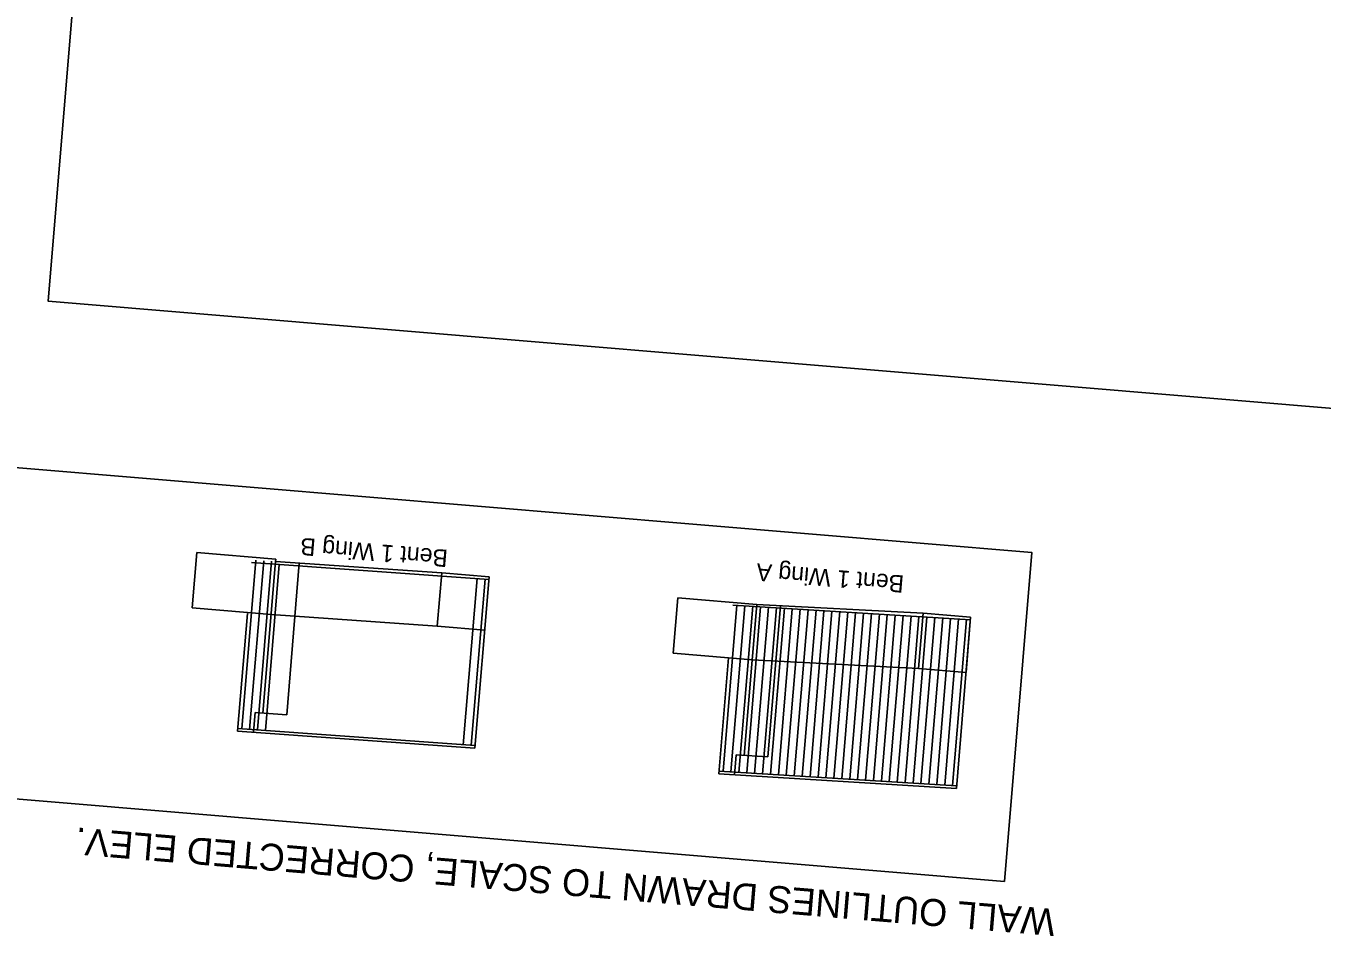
# Model space of a CAD drawing. Extents: x 1313815 to 1314857, y 2089008 to 2089414.
# Drawn here: x 1313873.4 to 1313955.2, y 2089107.2 to 2089164.5 of the extents above; entities that cross this region are included whole.
import ezdxf

# ---------------------------------------------------------------- set-up
doc = ezdxf.new("R2010")
doc.units = 0
for name, color, linetype in [('B-Gen-Construction Line', 7, 'Continuous'), ('B-Gen-Hidden', 7, 'Continuous'), ('B-Gen-Rebar', 7, 'Continuous'), ('B-Gen-Viewport', 7, 'Continuous'), ('B-Sub-Abutment Cap (Hidden)', 7, 'Continuous'), ('B-Sub-Wingwall', 7, 'Continuous')]:
    doc.layers.add(name, color=color, linetype=linetype)

msp = doc.modelspace()

# ---------------------------------------------------------------- linework, layer by layer
at = {"layer": 'B-Gen-Construction Line'}
for p, q in [((1313887.672, 2089130.726), (1313902.635, 2089129.658)), ((1313918.009, 2089128.043), (1313932.984, 2089127.125)), ((1313886.799, 2089120.263), (1313901.762, 2089119.194)), ((1313917.135, 2089117.58), (1313932.111, 2089116.661))]:
    msp.add_line(p, q, dxfattribs=at)
at = {"layer": 'B-Gen-Hidden'}
for p, q in [((1313890.678, 2089130.679), (1313889.882, 2089121.137)), ((1313921.016, 2089128.002), (1313920.22, 2089118.474)), ((1313887.782, 2089120.025), (1313887.887, 2089121.28)), ((1313887.783, 2089120.035), (1313887.886, 2089121.266)), ((1313887.887, 2089121.28), (1313889.882, 2089121.137)), ((1313886.785, 2089120.097), (1313901.748, 2089119.028)), ((1313918.12, 2089117.352), (1313918.224, 2089118.598)), ((1313918.12, 2089117.352), (1313918.222, 2089118.583)), ((1313918.224, 2089118.598), (1313920.22, 2089118.474)), ((1313917.121, 2089117.414), (1313932.097, 2089116.495))]:
    msp.add_line(p, q, dxfattribs=at)
at = {"layer": 'B-Gen-Rebar'}
for p, q in [((1313887.048, 2089120.245), (1313887.935, 2089130.875)), ((1313887.547, 2089120.209), (1313888.434, 2089130.839)), ((1313888.045, 2089120.174), (1313888.933, 2089130.803)), ((1313888.544, 2089120.138), (1313889.418, 2089130.602)), ((1313901.013, 2089119.248), (1313901.887, 2089129.711)), ((1313901.512, 2089119.212), (1313902.386, 2089129.676)), ((1313917.387, 2089117.586), (1313918.258, 2089128.029)), ((1313917.885, 2089117.545), (1313918.757, 2089127.998)), ((1313918.383, 2089117.503), (1313919.257, 2089127.967)), ((1313918.882, 2089117.473), (1313919.756, 2089127.936)), ((1313919.381, 2089117.442), (1313920.255, 2089127.906)), ((1313919.881, 2089117.411), (1313920.754, 2089127.875)), ((1313920.38, 2089117.381), (1313921.253, 2089127.844)), ((1313920.879, 2089117.35), (1313921.752, 2089127.814)), ((1313921.378, 2089117.32), (1313922.252, 2089127.783)), ((1313921.877, 2089117.289), (1313922.751, 2089127.753)), ((1313922.377, 2089117.258), (1313923.25, 2089127.722)), ((1313922.876, 2089117.228), (1313923.749, 2089127.691)), ((1313923.375, 2089117.197), (1313924.248, 2089127.661)), ((1313923.874, 2089117.166), (1313924.748, 2089127.63)), ((1313924.373, 2089117.136), (1313925.247, 2089127.599)), ((1313924.872, 2089117.105), (1313925.746, 2089127.569)), ((1313925.372, 2089117.074), (1313926.245, 2089127.538)), ((1313925.871, 2089117.044), (1313926.744, 2089127.507)), ((1313926.37, 2089117.013), (1313927.243, 2089127.477)), ((1313926.869, 2089116.983), (1313927.743, 2089127.446)), ((1313927.368, 2089116.952), (1313928.242, 2089127.416)), ((1313927.868, 2089116.921), (1313928.741, 2089127.385)), ((1313928.367, 2089116.891), (1313929.24, 2089127.354)), ((1313928.866, 2089116.86), (1313929.739, 2089127.324)), ((1313929.365, 2089116.829), (1313930.239, 2089127.293)), ((1313929.864, 2089116.799), (1313930.738, 2089127.262)), ((1313930.363, 2089116.768), (1313931.237, 2089127.232)), ((1313930.863, 2089116.738), (1313931.736, 2089127.201)), ((1313931.362, 2089116.707), (1313932.235, 2089127.171)), ((1313931.861, 2089116.676), (1313932.734, 2089127.14))]:
    msp.add_line(p, q, dxfattribs=at)
at = {"layer": 'B-Gen-Viewport'}
for points in [[(1314020.803, 2089135.014), (1313874.841, 2089147.198), (1313881.076, 2089221.883), (1314027.037, 2089209.699)], [(1313935.133, 2089110.63), (1313815.428, 2089120.622), (1313817.158, 2089141.347), (1313936.863, 2089131.354)]]:
    msp.add_lwpolyline(points, close=True, dxfattribs=at)
at = {"layer": 'B-Sub-Abutment Cap (Hidden)'}
for p, q in [((1313888.386, 2089121.242), (1313889.182, 2089130.786)), ((1313899.378, 2089126.708), (1313899.659, 2089130.074)), ((1313887.409, 2089127.581), (1313888.904, 2089127.456)), ((1313888.904, 2089127.456), (1313899.378, 2089126.708)), ((1313918.722, 2089118.559), (1313919.518, 2089128.091)), ((1313929.717, 2089124.052), (1313930.008, 2089127.54)), ((1313899.378, 2089126.708), (1313902.368, 2089126.458)), ((1313932.998, 2089127.291), (1313932.707, 2089123.803)), ((1313917.732, 2089124.728), (1313919.227, 2089124.604)), ((1313919.227, 2089124.604), (1313929.717, 2089124.052)), ((1313932.707, 2089123.803), (1313929.717, 2089124.052))]:
    msp.add_line(p, q, dxfattribs=at)
at = {"layer": 'B-Sub-Wingwall'}
for p, q in [((1313884.213, 2089131.36), (1313883.922, 2089127.872)), ((1313889.195, 2089130.944), (1313884.213, 2089131.36)), ((1313889.182, 2089130.786), (1313889.195, 2089130.944)), ((1313889.182, 2089130.786), (1313899.659, 2089130.074)), ((1313902.649, 2089129.824), (1313899.659, 2089130.074)), ((1313901.748, 2089119.028), (1313902.649, 2089129.824)), ((1313914.535, 2089128.507), (1313914.244, 2089125.019)), ((1313914.535, 2089128.507), (1313919.518, 2089128.091)), ((1313887.409, 2089127.581), (1313883.922, 2089127.872)), ((1313886.785, 2089120.097), (1313887.404, 2089127.513)), ((1313919.518, 2089128.091), (1313930.008, 2089127.54)), ((1313932.998, 2089127.291), (1313930.008, 2089127.54)), ((1313932.097, 2089116.495), (1313932.998, 2089127.291)), ((1313917.732, 2089124.728), (1313914.244, 2089125.019)), ((1313917.121, 2089117.414), (1313917.732, 2089124.728))]:
    msp.add_line(p, q, dxfattribs=at)

# ---------------------------------------------------------------- texts
at = {"layer": 'B-Gen-Construction Line'}
msp.add_text('WALL OUTLINES DRAWN TO SCALE, CORRECTED ELEV. ', height=1.69843, rotation=175.22842, dxfattribs=at).set_placement((1313938.38, 2089108.881))
at = {"layer": 'B-Sub-Abutment Cap (Hidden)'}
for s, p in [('Bent 1 Wing B', (1313900.077, 2089131.517)), ('Bent 1 Wing A', (1313928.832, 2089129.901))]:
    msp.add_text(s, height=1.09106, rotation=175.22842, dxfattribs=at).set_placement(p)

doc.saveas('drawing.dxf')
